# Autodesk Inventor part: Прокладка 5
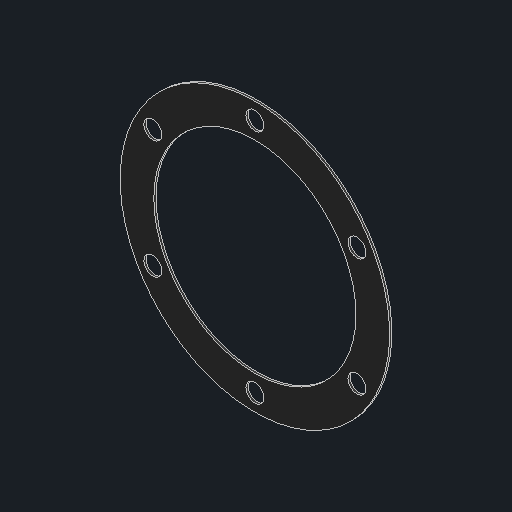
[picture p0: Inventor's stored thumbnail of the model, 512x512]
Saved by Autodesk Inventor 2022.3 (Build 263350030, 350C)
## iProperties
Created: 2022-08
Part Number: Прокладка 5
Material: Резина
Document SubType Name: Modeling
Designer: Карташов
Density: 0.93 g/cm^3
Appearance: Резина — черная
Author: Карташов
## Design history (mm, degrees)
sketch "Эскиз1"
  geometry: L1 (-320, -7.5)-(-320, 7.5) reference; L2 (-320, -7.5)-(-208, -7.5) reference; L3 (-68, -7.5)-(-25, -7.5) reference; L4 (105, -7.5)-(145, -7.5) reference; L5 (235, -7.5)-(320, -7.5) reference; L6 (320, 7.5)-(320, -7.5) reference; L7 (320, 7.5)-(248.095, 7.5) reference; L8 (195, 52.291)-(195, 82.5) reference; L9 (185, 82.5)-(195, 82.5) reference; L10 (185, 82.5)-(185, 52.291) reference; L11 (131.905, 7.5)-(118.581, 7.5) reference; L12 (70, 66.662)-(70, 77.5) reference; L13 (60, 77.5)-(70, 77.5) reference; L14 (60, 77.5)-(60, 69.96) reference; L15 (20, 69.96)-(20, 77.5) reference; L16 (10, 77.5)-(20, 77.5) reference; L17 (10, 77.5)-(10, 66.662) reference; L18 (-38.581, 7.5)-(-54.334, 7.5) reference; L19 (-108, 72.03)-(-108, 82.5) reference; L20 (-118, 82.5)-(-108, 82.5) reference; L21 (-118, 82.5)-(-118, 75.114) reference; L22 (-158, 75.114)-(-158, 82.5) reference; L23 (-168, 82.5)-(-158, 82.5) reference; L24 (-168, 82.5)-(-168, 72.03) reference; L25 (-221.666, 7.5)-(-320, 7.5) reference; L26 (-208, -7.5)-(-320, -7.5) reference; L27 (-320, -7.5)-(-320, -22.5) reference; L28 (-320, -22.5)-(-305, -22.5) reference; L29 (-300, -27.5)-(-300, -187.5) reference; L30 (-300, -187.5)-(-285, -187.5) reference; L31 (-285, -27.5)-(-285, -187.5) reference; L32 (-221.666, -22.5)-(-280, -22.5) reference; L33 (-38.581, -22.5)-(-54.334, -22.5) reference; L34 (131.905, -22.5)-(118.581, -22.5) reference; L35 (280, -22.5)-(248.095, -22.5) reference; L36 (285, -187.5)-(285, -27.5) reference; L37 (285, -187.5)-(300, -187.5) reference; L38 (300, -187.5)-(300, -27.5) reference; L39 (320, -22.5)-(305, -22.5) reference; L40 (320, -22.5)-(320, -7.5) reference; L41 (320, -7.5)-(235, -7.5) reference; L42 (145, -7.5)-(105, -7.5) reference; L43 (-25, -7.5)-(-68, -7.5) reference; C1 r 4 at (-138, 70) reference; C2 r 4 at (-2.614, 51.154) reference; C3 r 4 at (144.534, 18.75) reference; C4 r 4 at (190, 45) reference; C5 r 4 at (40, 65) reference; C6 r 4 at (-92.447, 55.199) reference; C7 r 4 at (-183.553, 55.199) reference; C8 r 4 at (-28.952, 14.904) reference; C9 r 4 at (108.952, 14.904) reference; C10 r 4 at (235.466, 18.75) reference; C11 r 4 at (82.614, 51.154) reference; C12 r 4 at (-64.293, 16.449) reference; C13 r 4 at (-211.707, 16.449) reference; C14 r 4 at (144.534, -33.75) reference; C15 r 4 at (235.466, -33.75) reference; C16 r 4 at (190, -60) reference; C17 r 4 at (82.614, -66.154) reference; C18 r 4 at (108.952, -29.904) reference; C19 r 4 at (-28.952, -29.904) reference; C20 r 4 at (-2.614, -66.154) reference; C21 r 4 at (40, -80) reference; C22 r 4 at (-92.447, -70.199) reference; C23 r 4 at (-64.293, -31.449) reference; C24 r 4 at (-211.707, -31.449) reference; C25 r 4 at (-183.553, -70.199) reference; C26 r 4 at (-138, -85) reference; C27 r 60 at (190, -7.5); A1 r 70 centre (-138, -7.5) between (-68, -7.5) and (-208, -7.5) reference; A2 r 65 centre (40, -7.5) between (105, -7.5) and (-25, -7.5) reference; A3 r 45 centre (190, -7.5) between (235, -7.5) and (145, -7.5) reference; A4 r 60 centre (190, -7.5) between (248.095, 7.5) and (195, 52.291) reference; A5 r 60 centre (190, -7.5) between (185, 52.291) and (131.905, 7.5) reference; A6 r 80 centre (40, -7.5) between (118.581, 7.5) and (70, 66.662) reference; A7 r 80 centre (40, -7.5) between (60, 69.96) and (20, 69.96) reference; A8 r 80 centre (40, -7.5) between (10, 66.662) and (-38.581, 7.5) reference; A9 r 85 centre (-138, -7.5) between (-54.334, 7.5) and (-108, 72.03) reference; A10 r 85 centre (-138, -7.5) between (-118, 75.114) and (-158, 75.114) reference; A11 r 85 centre (-138, -7.5) between (-168, 72.03) and (-221.666, 7.5) reference; A12 r 5 centre (-305, -27.5) between (-300, -27.5) and (-305, -22.5) reference; A13 r 5 centre (-280, -27.5) between (-280, -22.5) and (-285, -27.5) reference; A14 r 85 centre (-138, -7.5) between (-221.666, -22.5) and (-168, -87.03) reference; A15 r 85 centre (-138, -7.5) between (-168, -87.03) and (-158, -90.114) reference; A16 r 85 centre (-138, -7.5) between (-158, -90.114) and (-118, -90.114) reference; A17 r 85 centre (-138, -7.5) between (-118, -90.114) and (-108, -87.03) reference; A18 r 85 centre (-138, -7.5) between (-108, -87.03) and (-54.334, -22.5) reference; A19 r 80 centre (40, -7.5) between (-38.581, -22.5) and (10, -81.662) reference; A20 r 80 centre (40, -7.5) between (10, -81.662) and (20, -84.96) reference; A21 r 80 centre (40, -7.5) between (20, -84.96) and (60, -84.96) reference; A22 r 80 centre (40, -7.5) between (60, -84.96) and (70, -81.662) reference; A23 r 80 centre (40, -7.5) between (70, -81.662) and (118.581, -22.5) reference; A24 r 60 centre (190, -7.5) between (131.905, -22.5) and (160, -59.462) reference; A25 r 60 centre (190, -7.5) between (160, -59.462) and (170, -64.069) reference; A26 r 60 centre (190, -7.5) between (170, -64.069) and (210, -64.069) reference; A27 r 60 centre (190, -7.5) between (210, -64.069) and (220, -59.462) reference; A28 r 60 centre (190, -7.5) between (220, -59.462) and (248.095, -22.5) reference; A29 r 5 centre (280, -27.5) between (285, -27.5) and (280, -22.5) reference; A30 r 5 centre (305, -27.5) between (305, -22.5) and (300, -27.5) reference; A31 r 45 centre (190, -7.5) between (145, -7.5) and (235, -7.5) reference; A32 r 65 centre (40, -7.5) between (-25, -7.5) and (105, -7.5) reference; A33 r 70 centre (-138, -7.5) between (-208, -7.5) and (-68, -7.5) reference; 7 further points
  constraints: 1 centre point, 1 coincident, 1 concentric
extrude "Выдавливание1" new body sketch "Эскиз1" distance "d0" = 1; taper "d1" = 0 deg
node "Твердое тело1"
node "Ссылка1"
node "Ссылка2"
